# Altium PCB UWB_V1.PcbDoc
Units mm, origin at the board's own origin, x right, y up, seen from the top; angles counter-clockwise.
Board outline 57 x 40.78 mm, 2 copper layers (Top Layer, Bottom Layer); 72 components, 53 nets, 372 pads, 60 vias.
Unrouted connection lines stored in the file: 75.
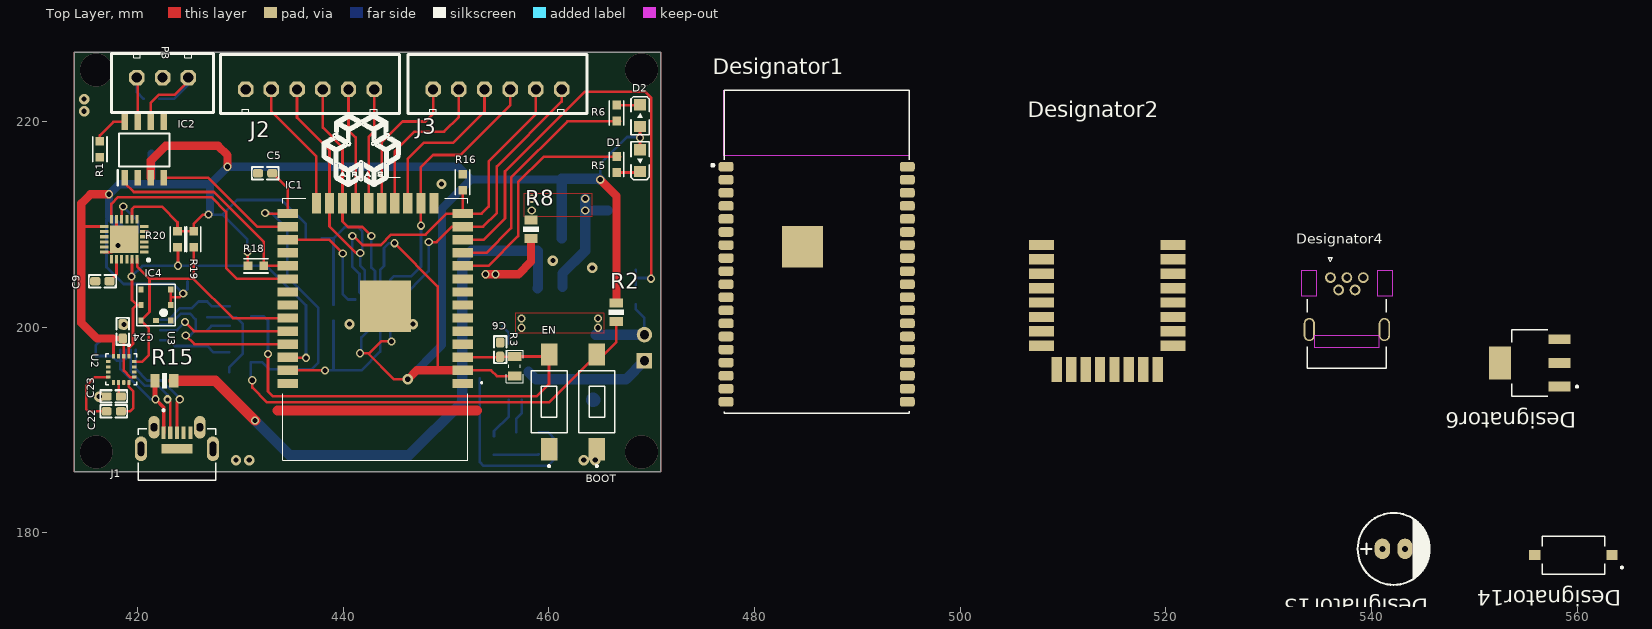
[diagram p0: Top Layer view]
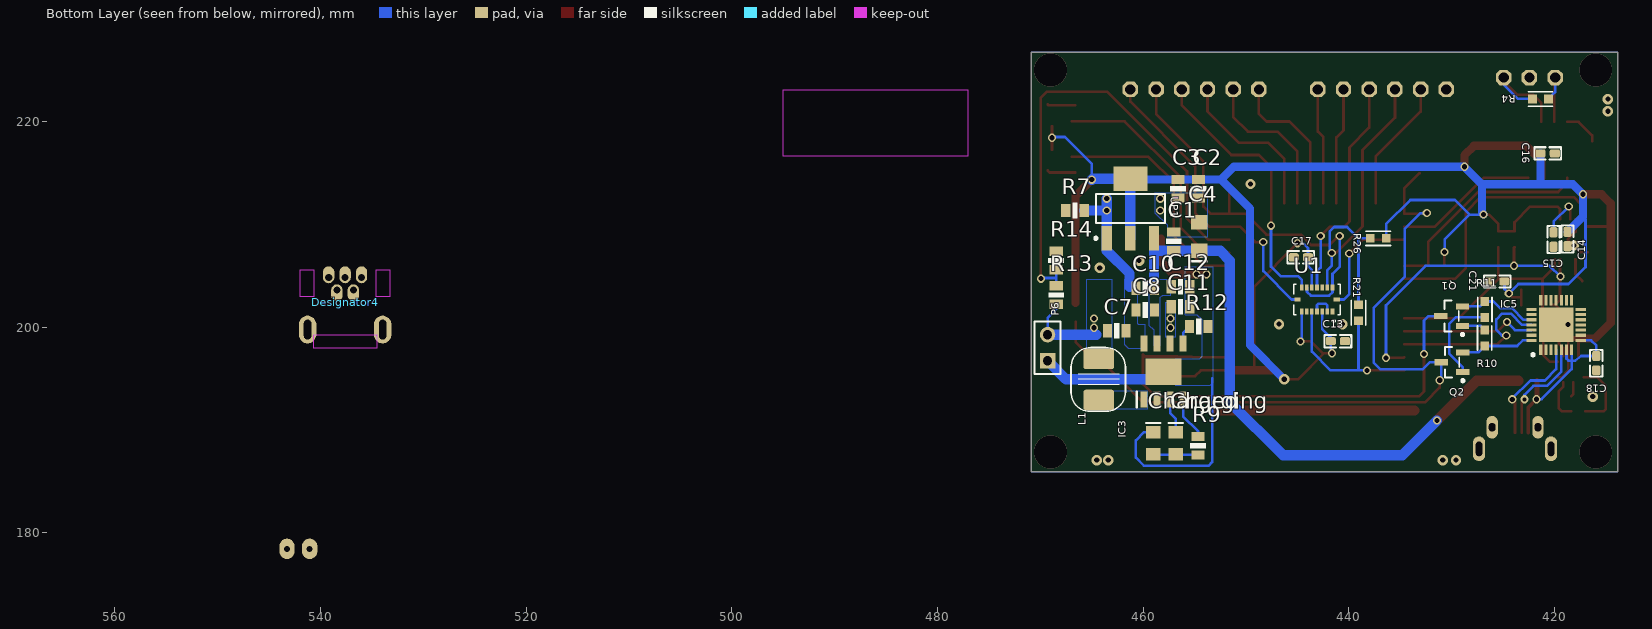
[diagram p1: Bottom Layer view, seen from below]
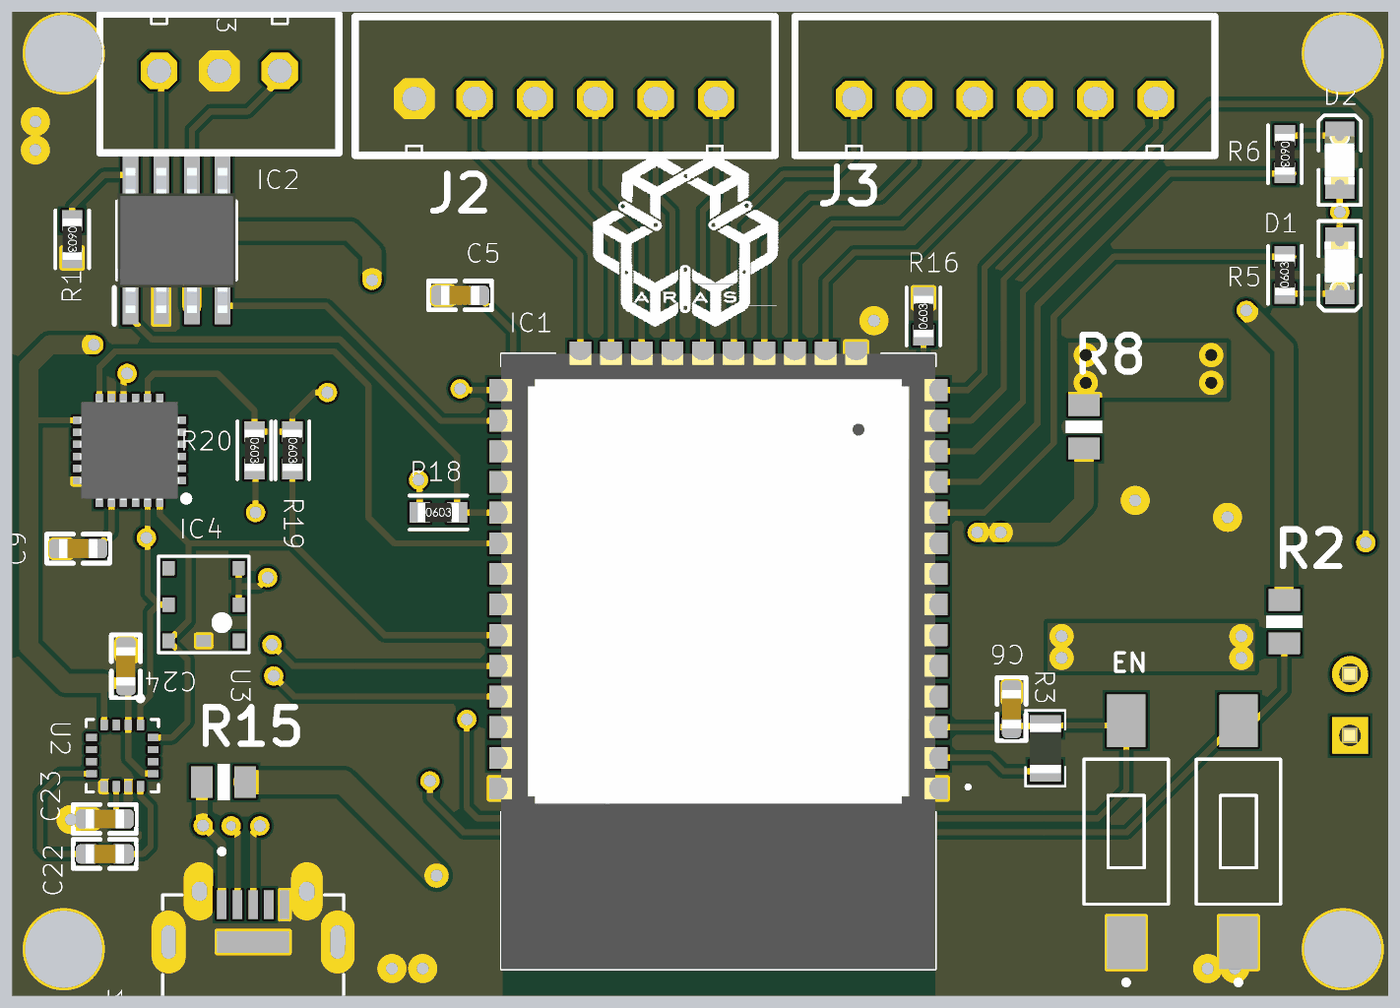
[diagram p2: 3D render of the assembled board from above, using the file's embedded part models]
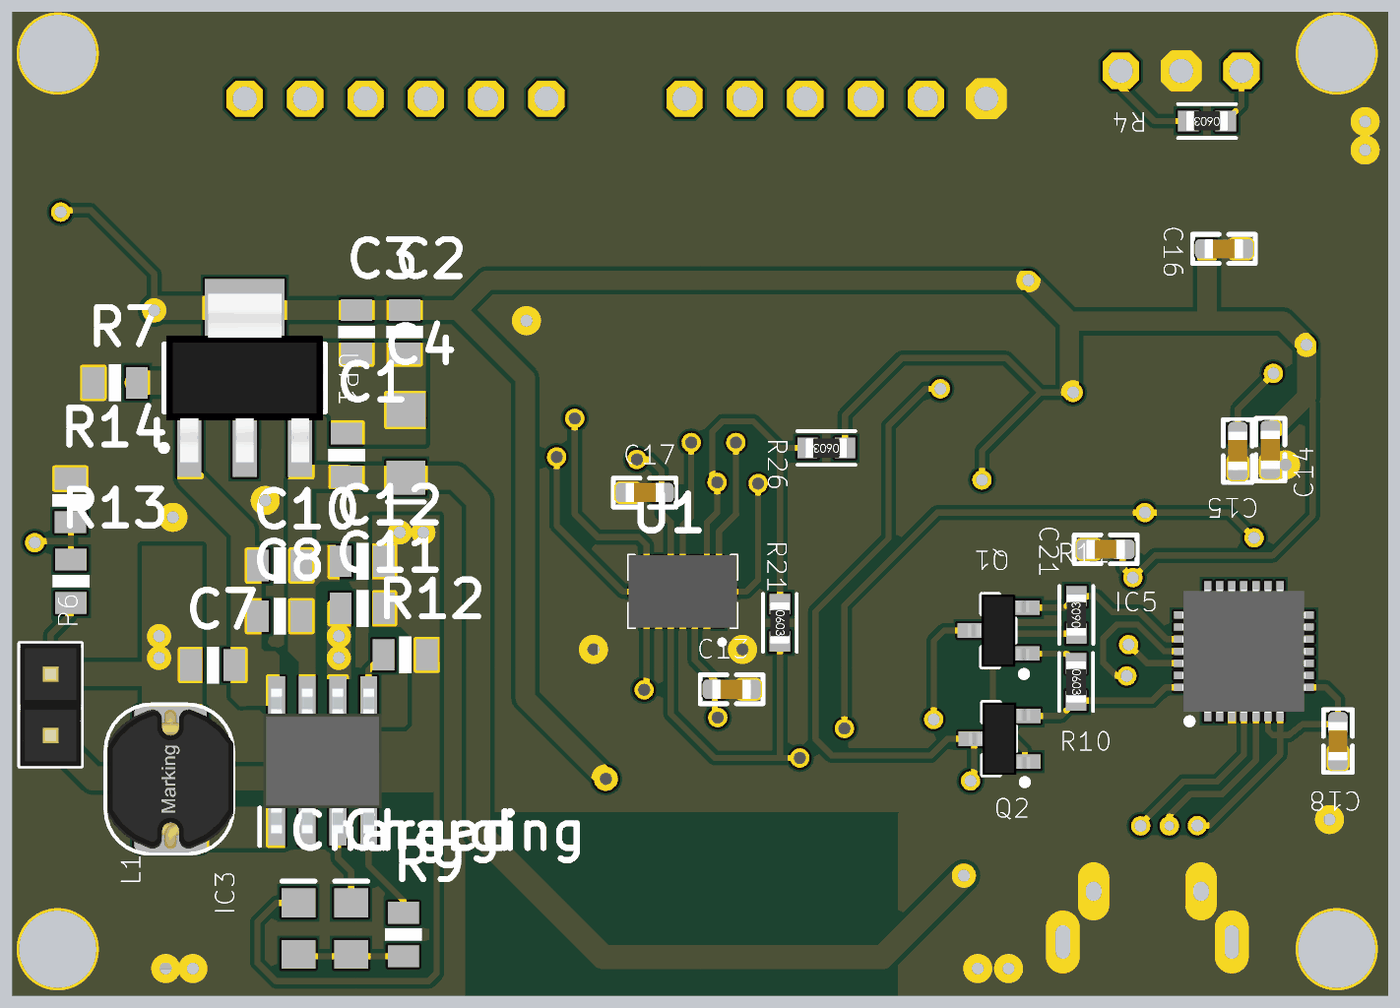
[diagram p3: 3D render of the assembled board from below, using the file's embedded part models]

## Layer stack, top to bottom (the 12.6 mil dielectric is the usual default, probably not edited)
Top Solder: solder mask 0.0102, Solder Resist, Dk 3.5
Top Layer: signal copper 0.0356
Dielectric 1: dielectric 0.32, FR-4, Dk 4.8
Bottom Layer: signal copper 0.0356
Bottom Solder: solder mask 0.0102, Solder Resist, Dk 3.5

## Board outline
413.875,185.95 470.875,185.95 470.875,226.725 413.875,226.725

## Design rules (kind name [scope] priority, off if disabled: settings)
Clearance [All] p1: gap=0.178 ignorepadtopadclearanceinfootprint=TRUE except(0: Arc-Hole Track-Hole SMDPad-Hole THPad-Hole Via-Hole Fill-Hole Poly-Hole Region-Hole Text-Hole)
PolygonConnect [All] p1: connectstyle=Direct reliefconductorwidth=0.254 reliefentries=4 polygonreliefangle="90 Angle" airgapwidth=0.254
RoutingVias [All] p1: holewidth=0.711 width=1.27 viastyle="Through Hole" minholewidth=0.711 minwidth=1.27 maxholewidth=0.711 maxwidth=1.27
SolderMaskExpansion [All] p1: expansion=0.102
Width [All] p1: maxlimit=2 minlimit=0.254 preferedwidth=0.254
30 further rules are at their usual default settings.

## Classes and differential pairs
component class final: BOOT C1 C2 C3 C4 C5 C6 C7 C8 C9 C10 C11 C12 C13 C14 C15 C16 C17 C18 C21 C22 C23 C24 Charged Charging D1 D2 D4 EN IC1 IC2 IC3 IC4 IC5 J1 J2 J3 L1 P3 P6 Q1 Q2 R1 R2 R3 R4 R5 R6 R7 R8 R9 R10 R11 R12 R13 R14 R15 R16 R18 R19 R20 R21 R26 U1 U2 U3 UP1

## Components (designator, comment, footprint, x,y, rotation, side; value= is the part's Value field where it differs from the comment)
BOOT "1437566-4" SW_1437566-4 464.675,192.75 r90 top
C1 "Cap" _0805 457.025,208.35 r90 bottom value=100nf
C2 "Cap" _0805 454.625,213.464 r270 bottom value=22uf
C3 "Cap" _0805 456.616,213.464 r270 bottom value=100NF
C4 "Cap-Pol" _EIA3216 454.575,208.825 r270 bottom value=22uf
C5 "0.1uF" C0603 432.425,214.975 r0 top
C6 "1nf" C0603 455.275,197.825 r270 top
C7 "Cap" _0805 462.575,199.653 r180 bottom value=10uf
C8 "Cap" _0805 459.8,201.678 r0 bottom value=22uf
C9 "220pF" C0603 416.6,204.475 r0 top
C10 "Cap" _0805 459.8,203.778 r0 bottom value=22uf
C11 "Cap" _0805 456.375,202 r180 bottom value=1uf
C12 "Cap" _0805 456.375,203.95 r180 bottom value=1uf
C13 "0.1uF" C0603 441.075,198.65 r0 bottom
C14 "0.1uF" C0603 418.75,208.575 r270 bottom
C15 "0.1uF" C0603 420.1,208.525 r90 bottom
C16 "100nF" C0603 420.675,216.9 r0 bottom
C17 "100nF" C0603 444.675,206.8 r180 bottom
C18 "100nF" C0603 415.95,196.5 r270 bottom
C21 "100nF" C0603 425.575,204.45 r180 bottom
C22 "0.22uF" C0603 417.7,191.825 r180 top
C23 "4.7uF" C0603 417.7,193.275 r0 top
C24 "100nF" C0603 418.575,199.6 r90 top
Charged "LED" _LED-0805 459.025,188.678 r90 bottom
Charging "LED" _LED-0805 456.838,188.678 r90 bottom
D1 "LED SMD PACKAGE" LED_SMD_0805 468.875,216.2 r90 top
D2 "LED SMD PACKAGE" LED_SMD_0805 468.875,220.575 r270 top
Designator1 "Comment" XCVR_ESP32-WROVER-I 486.05,207.35 r0 top
Designator2 "Comment" XCVR_DWM1000 514.3,206.2 r0 top
Designator4 "Comment" MOLEX_54819-0519 536,204.825 r0 top
Designator6 "Comment" SOT230P700X180-4N 555.375,196.525 r180 top
Designator13 "Comment" "cap 02" 542.15,178.45 r180 top
Designator14 "Comment" SW_TS09-63-25-R-160-SMT-TR 559.625,177.85 r180 top
EN "1437566-4" SW_1437566-4 460.025,192.75 r90 top
IC1 "ESP-WROOM-32D" ESPWROOM32D 443.125,199.8 r180 top
IC2 "SN65HVD230D" SOIC127P600X175-8N 420.675,217.25 r90 top
IC3 "ETA9742" SOIC127P600X175-9N 458.025,195.678 r90 bottom
IC4 "MPU-6050" QFN50P400X400X95-25N 418.725,208.55 r180 top
IC5 "CP2102_9" QFN50P500X500X105-29N-D 419.85,200.225 r90 bottom
J1 "UJ2-MIBH2-4-SMT-TR" CUI_UJ2-MIBH2-4-SMT-TR 423.85,187.625 r0 top
J2 "XH_6PIN" XH_6PIN 428.075,220.775 r0 top
J3 "XH_6PIN" XH_6PIN 446.3,220.775 r0 top
L1 "4µ7" "Inductor SMD 3x3.2mm" 464.325,194.928 r90 bottom
P3 "XH_3PIN" XH_3PIN 427.4,226.625 r180 top
P6 "Battery" HDR1X2 469.3,196.735 r90 bottom
Q1 "BC817" SOT23_N 430.011,201.081 r0 bottom
Q2 "BC817" SOT23_N 429.975,196.6 r0 bottom
R1 "Resistor SMD 0603" SMD-0603-RES 416.35,217.3 r180 top value=10K
R2 "Resistor" _0805 466.575,201.45 r270 top value=1K
R3 "10K" RES0805 456.675,196.2 r270 top
R4 "Resistor SMD 0603" SMD-0603-RES 421.375,222.2 r90 bottom value=120
R5 "Resistor SMD 0603" SMD-0603-RES 466.6,215.825 r0 top value=220
R6 "Resistor SMD 0603" SMD-0603-RES 466.6,220.825 r180 top value=220
R7 "Resistor" _0805 466.625,211.35 r0 bottom value=1K
R8 "Resistor" _0805 458.275,209.525 r90 top value=1K
R9 "Resistor" _0805 454.675,188.486 r90 bottom value=1K
R10 "Resistor SMD 0603" SMD-0603-RES 426.8,198.95 r0 bottom value=10K
R11 "Resistor SMD 0603" SMD-0603-RES 426.791,201.728 r180 bottom value=10K
R12 "Resistor" _0805 454.6,200.075 r0 bottom value=1K
R13 "Resistor" _0805 468.45,203.128 r270 bottom value=1K
R14 "Resistor" _0805 468.475,206.478 r270 bottom value=1K
R15 "Resistor" _0805 422.625,194.8 r0 top value=1K
R16 "Resistor SMD 0603" SMD-0603-RES 451.625,214.1 r0 top value=4.7k
R18 "Resistor SMD 0603" SMD-0603-RES 431.525,205.975 r270 top value=4.7k
R19 "Resistor SMD 0603" SMD-0603-RES 425.475,208.55 r180 top value=4.7k
R20 "Resistor SMD 0603" SMD-0603-RES 423.9,208.55 r180 top value=4.7k
R21 "Resistor SMD 0603" SMD-0603-RES 439.075,201.4 r0 bottom value=0
R26 "Resistor SMD 0603" SMD-0603-RES 437.15,208.65 r90 bottom value=4.7k
U1 "BMI088" PQFN50P450X300X100-16N 443.1,202.7 r0 bottom
U2 "HMC5883L-TR" XDCR_HMC5883L-TR 418.427,195.9 r270 top
U3 "BMP180" BMP180 421.8,202.16 r270 top
UP1 "3V3" SOT223_N 461.25,211.55 r90 bottom

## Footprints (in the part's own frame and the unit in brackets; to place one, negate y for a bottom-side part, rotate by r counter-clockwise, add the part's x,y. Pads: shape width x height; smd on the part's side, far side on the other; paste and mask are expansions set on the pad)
_0805 [mm]
  rect 0.9x1.3 smd: 1(-0.9,0) 2(0.9,0)
  silkscreen extent -0.25,-0.76 0.25,0.76
_EIA3216 [mm]
  rect 1.4x1.6 smd: +(1.4,0) -(-1.4,0)
  silkscreen extent 2.41,-0.76 2.41,0.76
_LED-0805 [mil]
  rect 47.24x55.12 smd: A(-40,0) K(44.06,0)
  silkscreen extent 79,-27 79,27
BMP180 [mm]
  rect 0.6x0.5 smd: 1(1.5,1.45) 2(0,1.45) 3(-1.5,1.45) 4(-1.5,-1.45) 5(0,-1.45) 6(1.5,-1.45)
  rect 0.5x0.6 smd: 7(1.5,0)
  silkscreen extent -2,-1.88 2,1.88
C0603 [mm] "CHIP Capacitor, 1.6X0.8mm, 0603 (Make www.tarahiboard.com)"
  rrect50% 1x0.8 smd mask+0.075: 1(-0.7,0) 2(0.7,0)
  silkscreen extent -1.33,-0.6 1.32,0.6, body extent -0.8,-0.4 0.8,0.4, height 0.9
"cap 02" [mm]
  oval 1.5x2 hole 0.6: 1(1.1,0) 2(-1.1,0)
  silkscreen extent -3.5,-3.5 3.5,3.5
CUI_UJ2-MIBH2-4-SMT-TR [mm]
  rect 0.4x1.2 smd: 1(-1.3,2.1) 2(-0.65,2.1) 3(0,2.1) 4(0.65,2.1) 5(1.3,2.1)
  oval 1.2x2.4 hole 0.6 slot 1.4 at 90 deg: SH1(-3.5,0.55) SH4(3.5,0.55)
  oval 1.1x2.2 hole 0.65 slot 0.8 at 90 deg: SH2(-2.225,2.65) SH3(2.225,2.65)
  rect 3x0.9 smd: SH5(0,0.55)
  silkscreen extent -3.75,-2.5 3.75,4.4
ESPWROOM32D [mm]
  rect 2x0.9 smd: 1(-8.5,5.26) 2(-8.5,3.99) 3(-8.5,2.72) 4(-8.5,1.45) 5(-8.5,0.18) 6(-8.5,-1.09) 7(-8.5,-2.36) 8(-8.5,-3.63) 9(-8.5,-4.9) 10(-8.5,-6.17) 11(-8.5,-7.44) 12(-8.5,-8.71) 13(-8.5,-9.98) 14(-8.5,-11.25) 25(8.5,-11.25) 26(8.5,-9.98) 27(8.5,-8.71) 28(8.5,-7.44) 29(8.5,-6.17) 30(8.5,-4.9) 31(8.5,-3.63) 32(8.5,-2.36) 33(8.5,-1.09) 34(8.5,0.18) 35(8.5,1.45) 36(8.5,2.72) 37(8.5,3.99) 38(8.5,5.26)
  rect 0.9x2 smd: 15(-5.715,-12.25) 16(-4.445,-12.25) 17(-3.175,-12.25) 18(-1.905,-12.25) 19(-0.635,-12.25) 20(0.635,-12.25) 21(1.905,-12.25) 22(3.175,-12.25) 23(4.445,-12.25) 24(5.715,-12.25)
  rect 5x5 smd: 39(-1,-2.24)
  silkscreen extent -10.4,-12.75 9,12.75, body extent -9,-12.75 9,12.75, height 3.1
HDR1X2 [mm] "Connector; Header; 2 Position"
  rect 1.5x1.5 hole 0.9: 1(0,0)
  round 1.5 hole 0.9: 2(2.54,0)
  silkscreen extent -1.27,-1.27 3.81,1.27, body extent -1.27,-1.28 3.81,1.26, height 8.79
"Inductor SMD 3x3.2mm" [mm] "Inductor 4.7µH SMD 3x3.2mm"
  round 0.508 on Mech15: 0(0,0)
  rrect25% 2x3 smd: 1(-2,0) 2(2,0)
  silkscreen extent -3.1,-2.6 3.1,2.7, body extent -2.9,-2.6 2.89,2.6, height 4.5
LED_SMD_0805 [mm] "SMD Mono-color Chip LED, body 2.0x1.25mm"
  rect 1.1x1.2 smd: 1(-1.05,0) 2(1.05,0)
  silkscreen extent -1.85,-0.88 1.85,0.88, body extent -1,-0.62 1,0.63, height 0.7
MOLEX_54819-0519 [mm]
  oval 1.1x1.65 smd far side paste-2 mask+0: 1(0,0.275) 2(0.8,-1.475) 3(1.6,0.275) 4(2.4,-1.475) 5(3.2,0.275)
  round 1.05 hole 0.7 mask+0.076: 6(0,0) 7(0.8,-1.2) 8(1.6,0) 9(2.4,-1.2) 10(3.2,0)
  oval 1.122x2.245 hole 0.7 slot 1.9 at 90 deg mask+0: 11(-2.05,-5.05) 12(5.25,-5.05)
  oval 1.7x2.7 smd far side paste-2 mask+0: S1(-2.05,-5.05) S2(5.25,-5.05)
  Keep-Out Layer region: 4.7,-6.8 -1.5,-6.8 -1.5,-5.6 4.7,-5.6
  Keep-Out Layer region: -1.4,-1.8 -2.8,-1.8 -2.8,0.7 -1.4,0.7
  Keep-Out Layer region: 6,-1.8 4.6,-1.8 4.6,0.7 6,0.7
  Keep-Out Layer region: -1.4,-1.8 -2.8,-1.8 -2.8,0.7 -1.4,0.7
  Keep-Out Layer region: 6,-1.8 4.6,-1.8 4.6,0.7 6,0.7
  Keep-Out Layer region: 4.7,-6.8 -1.5,-6.8 -1.5,-5.6 4.7,-5.6
  silkscreen extent -2.25,-8.8 5.45,1.95
PQFN50P450X300X100-16N [mm]
  rect 0.35x0.59 smd: 1(-1.5,1.165) 2(-1,1.165) 3(-0.5,1.165) 4(0,1.165) 5(0.5,1.165) 6(1,1.165) 7(1.5,1.165) 9(1.5,-1.165) 10(1,-1.165) 11(0.5,-1.165) 12(0,-1.165) 13(-0.5,-1.165) 14(-1,-1.165) 15(-1.5,-1.165)
  rect 0.59x0.35 smd: 8(1.915,0) 16(-1.915,0)
  silkscreen extent -2.25,-1.5 2.25,2.2, body extent -2.25,-1.5 2.25,1.5, height 1
QFN50P400X400X95-25N [mm]
  rect 0.8x0.3 smd: 1(-1.95,1.25) 2(-1.95,0.75) 3(-1.95,0.25) 4(-1.95,-0.25) 5(-1.95,-0.75) 6(-1.95,-1.25) 13(1.95,-1.25) 14(1.95,-0.75) 15(1.95,-0.25) 16(1.95,0.25) 17(1.95,0.75) 18(1.95,1.25)
  rect 0.3x0.8 smd: 7(-1.25,-1.95) 8(-0.75,-1.95) 9(-0.25,-1.95) 10(0.25,-1.95) 11(0.75,-1.95) 12(1.25,-1.95) 19(1.25,1.95) 20(0.75,1.95) 21(0.25,1.95) 22(-0.25,1.95) 23(-0.75,1.95) 24(-1.25,1.95)
  rect 2.75x2.65 smd: 25(0,0)
  silkscreen extent -2.48,1.88 -2.23,2.12, body extent -2.05,-2.05 2.05,2.05, height 0.95
QFN50P500X500X105-29N-D [mm]
  rect 1x0.3 smd: 1(-2.4,1.5) 2(-2.4,1) 3(-2.4,0.5) 4(-2.4,0) 5(-2.4,-0.5) 6(-2.4,-1) 7(-2.4,-1.5) 15(2.4,-1.5) 16(2.4,-1) 17(2.4,-0.5) 18(2.4,0) 19(2.4,0.5) 20(2.4,1) 21(2.4,1.5)
  rect 0.3x1 smd: 8(-1.5,-2.4) 9(-1,-2.4) 10(-0.5,-2.4) 11(0,-2.4) 12(0.5,-2.4) 13(1,-2.4) 14(1.5,-2.4) 22(1.5,2.4) 23(1,2.4) 24(0.5,2.4) 25(0,2.4) 26(-0.5,2.4) 27(-1,2.4) 28(-1.5,2.4)
  rect 3.35x3.35 smd: 29(0,0)
  silkscreen extent -3.02,2.13 -2.78,2.38, body extent -2.55,-2.55 2.55,2.55, height 1.05
RES0805 [mm] "Chip Resistor, 2-Leads, Body 2/00x1/25mm, IPC Medium Density DESIGNER:ABBAS BASEREH"
  rect 0.85x1.3 smd: 1(-0.95,0) 2(0.95,0)
  silkscreen extent -1.57,-0.82 1.58,0.83, body extent -1.02,-0.65 1.02,0.65, height 0.5
SMD-0603-RES [mm] "(Make www.tarahiboard.com)"
  rect 0.85x0.85 smd: 1(0,0.775) 2(0,-0.775)
  silkscreen extent -0.7,-1.2 0.7,1.2, body extent -0.4,-0.85 0.4,0.85, height 0.56
SOIC127P600X175-8N [mm]
  rect 1.525x0.65 smd: 1(-2.712,1.905) 2(-2.712,0.635) 3(-2.712,-0.635) 4(-2.712,-1.905) 5(2.712,-1.905) 6(2.712,-0.635) 7(2.712,0.635) 8(2.712,1.905)
  silkscreen extent -3.48,-2.45 1.6,2.58, body extent -3,-2.45 3,2.45, height 1.75
SOIC127P600X175-9N [mm]
  rect 1.55x0.7 smd: 1(-2.725,1.905) 2(-2.725,0.635) 3(-2.725,-0.635) 4(-2.725,-1.905) 5(2.725,-1.905) 6(2.725,-0.635) 7(2.725,0.635) 8(2.725,1.905)
  rect 2.6x3.5 smd: 9(0,0)
  silkscreen extent -3.5,2.61 -1.95,2.61, body extent -3,-2.45 3,2.45, height 1.75
SOT23_N [mm] "SOT23, 3-Leads, Body 2.9x1.3mm, Pitch 0.95mm, Lead Span 2.3mm, IPC Medium Density"
  rect 1.3x0.6 smd: 1(-1.05,0.95) 2(-1.05,-0.95) 3(1.05,0)
  silkscreen extent -1.17,-1.5 0.7,1.92, body extent -1.27,-1.5 1.27,1.5, height 1.1
SOT223_N [mm] "SOT223, 4-Leads, Body 6.5x3.5mm, Pitch 2.3mm, Lead Span 7mm, IPC Medium Density"
  rect 2.4x1 smd: 1(-2.9,2.3) 2(-2.9,0) 3(-2.9,-2.3)
  rect 2.4x3.3 smd: 4(2.9,0)
  silkscreen extent -3.02,-3.35 1.4,3.48, body extent -3.49,-3.24 3.49,3.24, height 1.64
SOT230P700X180-4N [mm]
  rect 2.15x0.95 smd: 1(-2.9,2.3) 2(-2.9,0) 3(-2.9,-2.3)
  rect 2.15x3.25 smd: 4(2.9,0)
  silkscreen extent -4.7,-3.25 1.75,3.25
SW_1437566-4 [mm]
  rect 2.18x1.6 smd: 1(-4.6,0) 2(4.6,0)
  silkscreen extent -6.35,-1.75 3,1.75
SW_TS09-63-25-R-160-SMT-TR [mm]
  rect 1.1x1 smd: 1(-3.75,0) 2(3.75,0)
  silkscreen extent -4.82,-1.85 3.05,1.85
XCVR_DWM1000 [mm]
  rect 2.45x1 smd: 1(-6.4,1.8) 2(-6.4,0.4) 3(-6.4,-1) 4(-6.4,-2.4) 5(-6.4,-3.8) 6(-6.4,-5.2) 7(-6.4,-6.6) 8(-6.4,-8) 17(6.4,-8) 18(6.4,-6.6) 19(6.4,-5.2) 20(6.4,-3.8) 21(6.4,-2.4) 22(6.4,-1) 23(6.4,0.4) 24(6.4,1.8)
  rect 1x2.45 smd: 9(-4.9,-10.295) 10(-3.5,-10.295) 11(-2.1,-10.295) 12(-0.7,-10.295) 13(0.7,-10.295) 14(2.1,-10.295) 15(3.5,-10.295) 16(4.9,-10.295)
XCVR_ESP32-WROVER-I [mm]
  rrect50% 1.45x0.93 smd: 1(-8.81,8.26) 2(-8.81,6.99) 3(-8.81,5.72) 4(-8.81,4.45) 5(-8.81,3.18) 6(-8.81,1.91) 7(-8.81,0.64) 8(-8.81,-0.63) 9(-8.81,-1.9) 10(-8.81,-3.17) 11(-8.81,-4.44) 12(-8.81,-5.71) 13(-8.81,-6.98) 14(-8.81,-8.25) 15(-8.81,-9.52) 16(-8.81,-10.79) 17(-8.81,-12.06) 18(-8.81,-13.33) 19(-8.81,-14.6) 20(8.81,-14.6) 21(8.81,-13.33) 22(8.81,-12.06) 23(8.81,-10.79) 24(8.81,-9.52) 25(8.81,-8.25) 26(8.81,-6.98) 27(8.81,-5.71) 28(8.81,-4.44) 29(8.81,-3.17) 30(8.81,-1.9) 31(8.81,-0.63) 32(8.81,0.64) 33(8.81,1.91) 34(8.81,3.18) 35(8.81,4.45) 36(8.81,5.72) 37(8.81,6.99) 38(8.81,8.26)
  rect 4x4 smd paste-3: 39(-1.38,0.47)
  Keep-Out Layer region: 9,9.33 -9.029,9.33 -9.029,15.7 9,15.7
  Keep-Out Layer region: 9,9.331 -9.03,9.331 -9.03,15.7 9,15.7
  silkscreen extent -10.22,-15.7 9,15.7
XDCR_HMC5883L-TR [mm]
  rrect17% 0.45x0.3 smd: 1(-1.275,0.75) 2(-1.275,0.25) 3(-1.275,-0.25) 4(-1.275,-0.75) 9(1.275,-0.75) 10(1.275,-0.25) 11(1.275,0.25) 12(1.275,0.75)
  rrect17% 0.3x0.45 smd: 5(-0.75,-1.275) 6(-0.25,-1.275) 7(0.25,-1.275) 8(0.75,-1.275) 13(0.75,1.275) 14(0.25,1.275) 15(-0.25,1.275) 16(-0.75,1.275)
  silkscreen extent -2.47,-1.5 1.5,1.5
XH_3PIN [mm]
  oct 1.5x1.5 hole 1: 1(2.45,2.35) 2(4.95,2.35) 3(7.45,2.35)
  silkscreen extent 0,0 9.9,5.75
XH_6PIN [mm]
  oct 1.5x1.5 hole 1: 1(2.45,2.35) 2(4.95,2.35) 3(7.45,2.35) 4(9.95,2.35) 5(12.45,2.35) 6(14.95,2.35)
  silkscreen extent 0,0 17.4,5.75

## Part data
BOOT EN: "Switch Tactile OFF _ON_ SPST Rectangular Button Gull Wing 0.05A 12VDC 1.77N SMD T/R", Contact_Current_Rating="50 mA", Package=None
C1 C2 C3 C7 C8 C10 C11 C12: library part Cap_1
C5 C6 C9 C13 C14 C15 C16 C17 C18 C21 C22 C23 C24: library part "CAP SMD 0805", "CAP 0805"
D1 D2: "SMD Mono-color Chip LED Waterclear", Forward Voltage="3.2 V", Part Number=150080BS75000
IC1: "Integrated Circuit", Manufacturer_Name="Espressif Systems", Mouser Part Number=356-ESP-WROOM-32D
IC2: "Integrated Circuit", Manufacturer_Name="Texas Instruments", Mouser Part Number=595-SN65HVD230D
IC3: "Integrated Circuit", Manufacturer_Name="ETA Solutions"
IC4: "Integrated Circuit", Manufacturer_Name=TDK, Mouser Part Number=410-MPU-6050
IC5: "Integrated Circuit", Manufacturer_Name="Silicon Labs", Manufacturer_Part_Number=CP2102/9
J1: "Micro B, USB 2.0, 1.8 A, Right Angle, Surface Mount _SMT_, USB Receptacle", Package=None
L1: library part "Inductor 4.7µH SMD 3x3.2mm", "Inductor 4.7µH SMD 3x3.2mm", Operating Temperature="-40°C ~ 125°C", Tolerance=±20%
P6: library part "Header 2", "Header, 2-Pin"
Q1 Q2: "45 V, 500 mA NPN general-purpose transistors"
R3: library part "RES SMD PACKAGE", "TOTAL SMD RESISTOR PACK"
U1: "Accelerometer, Gyroscope, 6 Axis Sensor I²C, SPI Output", Package="VFLGA-16 Bosch Sensortec"
U2: "Magnetoresistive Sensor X, Y, Z Axis 16-LCC", Package="LCC-16 Honeywell"
U3: "Pressure Sensor 4.35PSI ~ 15.95PSI _30kPa ~ 110kPa_ Absolute 16 ~ 19 b 7-VLGA", Package="VLGA-7 Bosch Sensortec"
UP1: library part AMS1117-x.x, "x.x Volt, 800mA Low-Dropout Linear Regulator, 4-pin SOT-223"

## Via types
v1: diameter 0.8, hole 0.5, Top Layer to Bottom Layer, 40 vias
v2: diameter 1, hole 0.5, Top Layer to Bottom Layer, 15 vias
v3: diameter 3.2, hole 3.2, Top Layer to Bottom Layer, 4 vias
v4: diameter 0.8, hole 0.4, Top Layer to Bottom Layer, 1 vias

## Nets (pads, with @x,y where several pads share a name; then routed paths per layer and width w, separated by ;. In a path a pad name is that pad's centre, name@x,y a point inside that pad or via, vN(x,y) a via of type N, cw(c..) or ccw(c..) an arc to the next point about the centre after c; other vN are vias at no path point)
3v3: C2.1 C3.1 C13.2 C14.1 C16.2 C17.2 C21.2 C24.1 D1.2 D2.2 IC1.2 IC2.3 IC4.8 IC4.13 R2.1 R3.2 R18.2 R19.2 R20.2 R26.2 U1.3 U1.7 U1.11 U2.2 U2.4 U2.13 U3.2 U3.3 UP1.2 UP1.4 | length 241.6
  Top Layer w0.254: 414.55,209.75 414.6,209.8 IC4.13 ; 417.625,198.9 417.677,198.848 U2.4 ; C24.1 418.677,198.798 U2.2 418.677,195.773 419.295,195.155 419.702,195.155 U2.13 ; IC4.8 419.475,211.475 419.725,211.725 422.375,211.725 423.9,210.2 R20.2 R19.2 425.475,210.05 426.375,210.95 v1(426.925,210.95) ; U3.2 423.25,202.91 ; U3.3 423.25,202.91 ; v1(424.45,203.275) 424.085,202.91 423.25,202.91 ; v1(430.7,207.325) 430.75,207.275 R18.2 ; v1(441.65,197.475) 442.4,197.475 ; v1(444.7,198.625) 443.7,198.625 442.55,197.475 442.4,197.475 ; v1(445,208.175) 449.2,203.975 449.2,195.86 449.25,195.81 ; v2(446.287,194.937) 444.938,194.937 442.4,197.475 ; IC1.2 454.39,195.81 454.95,195.25 R3.2 ; D1.2 v1(468.875,218.425) D2.2
  Top Layer w0.5: 417.625,198.9 C24.1
  Top Layer w0.8: v1(417.25,212.925) 415.425,212.925 414.55,212.05 414.55,209.75 414.55,200.425 416.075,198.9 417.625,198.9 ; IC2.3 421.31,216.21 422.739,217.639 427.861,217.639 428.775,216.725 v1(428.775,215.6) ; v2(446.287,194.937) 447.16,195.81 449.25,195.81 IC1.2 ; v1(465,214.35) 466.575,212.775 R2.1
  Bottom Layer w0.254: 417.25,210.775 417,210.525 417,205.85 418.65,204.2 423.525,204.2 v1(424.45,203.275) 424.875,203.7 C21.2 ; v1(426.925,210.95) 428.275,210.95 ; v1(430.7,207.325) 430.7,208.525 428.275,210.95 ; R26.2 436.375,210.025 434.025,212.375 429.7,212.375 428.275,210.95 ; v1(441.65,197.475) 441.775,197.6 C13.2 441.775,199.025 442.6,199.85 U1.3 ; U1.11 443.6,205.575 443.975,205.95 C17.2 443.975,207.7 444.45,208.175 v1(445,208.175) ; U1.7 444.6,198.725 v1(444.7,198.625) ; v1(465,214.35) 465,215.875 467.625,218.5 v1@469.1,218.5
  Bottom Layer w0.4: C14.1@418.65,209.175 C14.1
  Bottom Layer w0.8: C14.1 417.25,210.775 v1(417.25,212.925) 418.225,213.9 421.325,213.9 ; C16.2 421.375,213.95 421.325,213.9 ; v1(426.925,210.95) 427.075,211.1 427.075,213.9 ; v2(446.287,194.937) 449.625,198.275 449.625,211.55 452.439,214.364 ; UP1.4@461.164,214.364 C3.1 C2.1 452.439,214.364 ; 421.325,213.9 427.075,213.9 ; 427.075,213.9 v1(428.775,215.6) 451.203,215.6 452.439,214.364
  Bottom Layer w1: UP1.4@461.164,214.364 461.25,214.278 UP1.2 ; UP1.4 464.9,214.45 v1(465,214.35)
5V: C1.1 C4.+ C8.1 C10.1 C12.1 IC3.7 R15.2 UP1.3 | length 58.4
  Top Layer w1: R15.2 427.575,194.8 v1(431.45,190.925)
  Bottom Layer w1: v1(431.45,190.925) 434.825,187.55 446.4,187.55 451.575,192.725 451.575,206.475 452.525,207.425 C4.+ 457,207.425 C1.1 458.875,207.45 458.95,207.375 458.95,203.828 C10.1
21: IC1.21 J2.5 | length 11.4
  Top Layer w0.254: J2.5 440.525,219.15 441.22,218.455 IC1.21
AGND: C11.2 C12.2 Charged.K IC3.9 P6.1 R8.1 R12.1 | length 39.3
  Top Layer w0.8: v1(453.85,205.15) v1(454.825,205.15) 457.05,205.15 458.275,206.375 R8.1
  Bottom Layer w0.254: 453.3,195.05 453.3,186.875 453.625,186.55 459.95,186.55 460.725,187.325 460.725,189 459.928,189.797 Charged.K
  Bottom Layer w1: IC3.9 458.753,194.95 467.515,194.95 P6.1
Bat: C7.1 C11.1 IC3.6 L1.2 P6.2 R13.2 | length 8
  Bottom Layer w0.254: R13.2 468.45,201.75 469.3,200.9 P6.2
  Bottom Layer w1: 464.575,199.275 P6.2
  other v1: 457.35,199.95 464.8,199.95 457.35,200.85 464.8,200.85
Bat_Sense: IC1.12 R13.1 R14.2 | length 47.9
  Top Layer w0.254: IC1.12 453.685,208.51 455.75,210.575 455.75,215.15 463.5,222.9 469.375,222.9 469.95,222.325 v1(469.95,204.725)
  Bottom Layer w0.254: R13.1 468.45,204.791 ; R14.2 468.45,205.553 468.45,204.791 ; v1(469.95,204.725) 469.884,204.791 468.45,204.791
"CAN RX": IC1.26 IC2.4 | length 14
  Top Layer w0.254: IC2.4 426.887,214.538 431.645,209.78 IC1.26
"CAN TX": IC1.29 IC2.1 R18.1 | length 21.1
  Top Layer w0.254: IC2.1 418.77,214.03 419.65,213.15 427.45,213.15 432.3,208.3 R18.1 432.305,205.97 IC1.29
CS_ACC: IC1.23 J2.3 R21.2 R26.1 U1.14 | length 35.5
  Top Layer w0.254: J2.3 435.525,220.375 438.68,217.22 IC1.23 438.68,209.795 441.25,207.225 v1(441.675,207.225)
  Bottom Layer w0.254: R26.1 439.075,208.65 ; R21.2 439.075,208.65 ; U1.14 442.1,205.55 441.675,205.975 v1(441.675,207.225) 441.875,207.425 441.875,209.325 441.45,209.75 440.175,209.75 439.075,208.65
CS_GYR: IC1.37 R21.1 U1.5 | length 18.5
  Top Layer w0.254: IC1.37 438.24,195.81 v1(438.25,195.8)
  Bottom Layer w0.254: v1(438.25,195.8) 439.075,195.8 ; R21.1 439.075,195.8 ; U1.5 443.6,197.625 441.775,195.8 439.075,195.8
EN: C6.2 EN.2 IC1.3 Q1.3 R3.1 | length 48.1
  Top Layer w0.254: v1(432.7,197.4) 432.7,193.75 433.15,193.3 458.85,193.3 460.025,194.475 EN.2 459.825,197.15 R3.1 456.65,197.125 C6.2 455.23,197.08 IC1.3
  Bottom Layer w0.254: Q1.3 432.269,201.081 432.7,200.65 v1(432.7,197.4)
GND: BOOT.1 C5.1 C6.1 C9.1 C13.1 C14.2 C15.1 C16.1 C17.1 C18.2 C21.1 C23.1 C24.2 EN.1 IC1.1 IC1.15 IC1.38 IC1.39 IC2.2 IC4.11 IC4.18 IC4.25 IC5.3 IC5.29 J1.5 J1.SH1 J1.SH2 J1.SH3 J1.SH4 J1.SH5 J2.1 P3.2 R1.1 R7.2 R14.1 R16.1 U1.2 U1.4 U1.6 U2.9 U2.11 U3.7 | length 26.4
  Top Layer w0.254: IC4.18 416.775,207.305 417.48,207.305 IC4.25 417.975,209.3 IC4.11
  Top Layer w1: 433.625,191.9 453,191.9
  Bottom Layer w0.254: U1.2 442.1,202.125 442.275,202.3 442.95,202.3 443.1,202.15 U1.4
  other v2: 429.6,187.075 430.875,187.075 463.4,187.075 464.525,187.075 416.3,193.25 418.7,200.25 440.625,200.3 446.8,200.3 464.225,205.775 460.4,206.475 418.125,207.95 449.575,213.925 414.825,221 414.825,222.175
  other v3: 416,187.875 469,187.875 416,225 469,225
INT1: IC1.27 U1.16 | length 11.3
  Top Layer w0.254: IC1.27 438.64,208.51 v1(439.975,207.175)
  Bottom Layer w0.254: v1(439.975,207.175) 439.975,203.2 440.475,202.7 U1.16
INT2: IC1.22 J2.4 U1.12 | length 22.2
  Top Layer w0.254: J2.4 438.025,219.4 439.95,217.475 IC1.22 439.95,210.3 440.5,209.75 441.875,209.75 v1(442.75,208.875)
  Bottom Layer w0.254: v1(442.75,208.875) 442.75,205.8 443.1,205.45 U1.12
INT_MPU: IC1.30 IC4.12 | length 25.4
  Top Layer w0.254: IC4.12 417.475,212 418.125,212.65 427.2,212.65 428.625,211.225 428.625,205.775 429.7,204.7 IC1.30
IO0: BOOT.2 C5.2 IC1.25 Q2.3 R2.2 | length 73.9
  Top Layer w0.254: v1(431.175,194.85) 431.175,194.125 432.575,192.725 460.05,192.725 BOOT.2 465.35,197.35 466.575,198.575 R2.2 ; v1(432.425,211.1) 432.475,211.05 IC1.25 434.625,213.475 C5.2
  Bottom Layer w0.254: v1(431.175,194.85) 431.025,195 Q2.3 432.125,196.6 432.825,195.9 436.925,195.9 437.6,196.575 437.6,201.875 434.575,204.9 434.575,209.575 433.05,211.1 v1(432.425,211.1)
IO1: IC1.24 J2.2 | length 12.9
  Top Layer w0.254: J2.2 433.025,220.975 437.41,216.59 IC1.24
IO5: IC1.20 J2.6 | length 11.3
  Top Layer w0.254: IC1.20 442.49,218.49 443.025,219.025 J2.6
IO6: IC1.19 J3.1 | length 14.4
  Top Layer w0.254: IC1.19 443.76,217.96 445.8,220 448,220 448.75,220.75 J3.1
IO7: IC1.18 J3.2 | length 15.4
  Top Layer w0.254: IC1.18 445.03,217.13 446.925,219.025 449.825,219.025 451.25,220.45 J3.2
IO8: IC1.17 J3.3 | length 15.8
  Top Layer w0.254: IC1.17 446.3,216.4 447.85,217.95 450.725,217.95 453.75,220.975 J3.3
IO9: IC1.16 J3.4 U1.9 | length 26.7
  Top Layer w0.254: v1(447.575,209.875) 447.57,209.88 IC1.16 447.57,215.57 448.75,216.75 451.425,216.75 456.25,221.575 J3.4
  Bottom Layer w0.254: U1.9 444.6,204.625 444.925,204.95 446.625,204.95 447.575,205.9 v1(447.575,209.875)
IO10: IC1.14 J3.5 R16.2 U1.10 U1.15 | length 39.7
  Top Layer w0.254: v1(440.9,208.875) 441.022,208.875 441.897,208 443.675,208 444.675,209 448.025,209 450.075,211.05 IC1.14 ; R16.2 IC1.14 ; J3.5 458.75,220.725 454.15,216.125 454.15,211.725 453.475,211.05 IC1.14
  Bottom Layer w0.254: v1(440.9,208.875) 440.9,205.95 440.875,205.925 441.6,205.2 U1.15 441.6,203.4 441.925,203.075 443.711,203.075 444.08,203.444 444.08,203.845 U1.10
IO11: IC1.13 J3.6 U1.8 | length 29.7
  Top Layer w0.254: v1(448.325,208.275) 449.1,208.275 450.605,209.78 IC1.13 453.605,209.78 454.95,211.125 454.95,215.625 461.25,221.925 J3.6
  Bottom Layer w0.254: U1.8 445.575,202.7 448.325,205.45 v1(448.325,208.275)
NetC9_2: C9.2 IC4.20 | length 2.4
  Top Layer w0.254: C9.2 417.975,205.15 IC4.20
NetC15_2: C15.2 IC4.10 | length 4.4
  Top Layer w0.254: IC4.10 418.475,211.59 v1(418.625,211.74)
  Bottom Layer w0.254: v1(418.625,211.74) 420.1,210.265 C15.2
NetC18_1: C18.1 IC5.6 IC5.7 IC5.8 J1.1 R15.1 | length 18.7
  Top Layer w0.35: v1@421.725,193.05 v1(421.775,193) 422.55,192.225 J1.1
  Top Layer w0.5: v1@421.725,193.05 R15.1
  Bottom Layer w0.254: IC5.8 416.45,198.725 415.95,198.225 C18.1 417.417,197.2 417.992,196.75 418.35,196.75 ; IC5.7 418.35,196.75 ; IC5.6 418.85,196.95 418.65,196.75 418.35,196.75 ; v1(421.775,193) 421.275,193 418.35,195.925 418.35,196.75
NetC22_1: C22.1 U2.12 | length 4
  Top Layer w0.254: C22.1 419.285,191.825 419.6,192.14 419.6,193.775 419.177,194.198 U2.12
NetC22_2: C22.2 U2.8 | length 6.8
  Top Layer w0.254: C22.2 415.25,191.825 415.025,192.05 415.025,194.3 415.875,195.15 U2.8
NetC23_2: C23.2 U2.10 | length 1.4
  Top Layer w0.254: U2.10 418.177,193.498 C23.2
NetCharged_A: Charged.A Charging.A R9.1 | length 4.4
  Bottom Layer w0.254: R9.1 458.949,187.586 Charged.A
NetCharging_K: Charging.K IC3.3 | length 3.4
  Bottom Layer w0.254: Charging.K 456.838,191.088 457.39,191.64 IC3.3
NetD1_1: D1.1 R5.2 | length 2.8
  Top Layer w0.254: R5.2 469.1,215.05 D1.1@469.3,215.25
NetD2_1: D2.1 R6.2 | length 2.7
  Top Layer w0.254: R6.2 469.225,221.6 D2.1@469.3,221.675
NetIC1_10: IC1.10 R5.1 | length 22.8
  Top Layer w0.254: IC1.10 454.145,205.97 457.025,208.85 457.025,214.1 459.5,216.575 R5.1@466.95,216.575
NetIC1_11: IC1.11 R6.1 | length 23.5
  Top Layer w0.254: IC1.11 453.94,207.24 456.35,209.65 456.35,214.55 461.825,220.025 R6.1@466.95,220.025
NetIC2_6: IC2.6 P3.1 R4.1 | length 10.8
  Top Layer w0.254: IC2.6 421.31,221.835 422.074,222.599 423.624,222.599 424.95,223.925 P3.1
  Bottom Layer w0.254: R4.1 423.55,222.2 424.95,223.6 P3.1
NetIC2_7: IC2.7 P3.3 R4.2 | length 6.7
  Top Layer w0.254: P3.3 420.04,224.185 IC2.7
  Bottom Layer w0.254: P3.3 419.95,222.85 R4.2
NetIC2_8: IC2.8 R1.2 | length 3.5
  Top Layer w0.254: R1.2 416.35,218.65 417.662,219.962 IC2.8
NetIC3_1: IC3.1 L1.1 | length 0
  Bottom Layer w1.4: L1.1@464.3,192.953 L1.1
NetIC3_4: IC3.4 R9.2 | length 4.2
  Bottom Layer w0.254: R9.2 454.675,189.9 456.12,191.345 IC3.4
NetIC3_5: IC3.5 R12.2 | length 1.9
  Bottom Layer w0.254: R12.2 456.12,199.455 IC3.5
NetIC5_4: IC5.4 J1.3 | length 10.7
  Top Layer w0.254: J1.3 423.85,192.713 v1(424.125,192.988)
  Bottom Layer w0.254: IC5.4 419.85,195.925 420.95,194.825 422.35,194.825 v1@424.125,193.05
NetIC5_5: IC5.5 J1.2 | length 10.5
  Top Layer w0.254: v4(422.938,192.988) 423.2,192.725 J1.2
  Bottom Layer w0.254: IC5.5 419.35,195.7 420.75,194.3 422.05,194.3 422.938,193.412 v4(422.938,192.988)
NetIC5_24: IC5.24 Q1.2 R11.1 | length 7.6
  Bottom Layer w0.254: IC5.24 423.039,200.725 424.164,201.85 425.3,201.85 425.953,202.503 R11.1 427.262,202.031 Q1.2
NetIC5_28: IC5.28 Q2.2 R10.1 | length 7.2
  Bottom Layer w0.254: IC5.28 423.1,198.725 423.65,198.175 R10.1 427.425,197.55 Q2.2
NetQ1_1: Q1.1 R10.2 | length 2.3
  Bottom Layer w0.254: R10.2 427.206,200.131 Q1.1
NetQ2_1: Q2.1 R11.2 | length 8.9
  Bottom Layer w0.254: R11.2 429.622,200.953 430.25,200.325 430.25,197.425 428.925,196.1 Q2.1
PGND: C1.2 C2.2 C3.2 C4.- C7.2 C8.2 C10.2 IC3.8 R7.1 R8.2 UP1.1 | length 11.7
  Bottom Layer w1: 461.325,203.925 461.325,205.225 463.55,207.45 UP1.1 v1(463.55,211.35) ; v1(463.55,212.5) v1(463.55,211.35) ; R7.1 v1(463.55,211.35)
  other v1: 458.35,211.35 458.35,212.5
RXD0: IC1.35 IC5.25 | length 16.6
  Top Layer w0.254: v1(424.7,199.2) 425.55,198.35 IC1.35
  Bottom Layer w0.254: IC5.25 423.15,200.225 424.25,201.325 425.125,201.325 425.675,200.775 425.675,199.75 425.125,199.2 v1(424.7,199.2)
SCL: IC1.36 IC4.23 R20.1 U2.1 U3.5 | length 38.1
  Top Layer w0.254: U2.1 419.177,197.977 419.575,198.375 419.575,201.825 419.91,202.16 419.94,202.16 ; IC4.23 419.475,202.625 419.94,202.16 ; U3.5 419.94,202.16 ; R20.1 423.95,207.725 v1(423.95,205.975) ; IC1.36 434.68,197.025 v1(436.4,197.025)
  Bottom Layer w0.254: v1(419.425,204.925) 420.475,205.975 v1(423.95,205.975) 432.55,205.975 436.4,202.125 v1(436.4,197.025)
SDA: IC1.33 IC4.24 R19.1 U2.16 U3.6 | length 30.3
  Top Layer w0.254: U2.16 420.475,196.65 421.125,197.3 421.125,199.885 U3.6 421.175,201.485 421.175,204.7 ; IC4.24 419.975,205.9 421.175,204.7 ; R19.1 425.475,204.7 ; IC1.33 429.285,200.89 425.475,204.7 ; 421.175,204.7 425.475,204.7
TXD0: IC1.34 IC5.26 | length 13.1
  Top Layer w0.254: v1(424.625,200.5) 425.505,199.62 IC1.34
  Bottom Layer w0.254: IC5.26 423.85,199.725 v1(424.625,200.5)
pads on no net: Designator1.1 Designator1.2 Designator1.3 Designator1.4 Designator1.5 Designator1.6 Designator1.7 Designator1.8 Designator1.9 Designator1.10 Designator1.11 Designator1.12 Designator1.13 Designator1.14 Designator1.15 Designator1.16 Designator1.17 Designator1.18 Designator1.19 Designator1.20 Designator1.21 Designator1.22 Designator1.23 Designator1.24 Designator1.25 Designator1.26 Designator1.27 Designator1.28 Designator1.29 Designator1.30 Designator1.31 Designator1.32 Designator1.33 Designator1.34 Designator1.35 Designator1.36 Designator1.37 Designator1.38 Designator1.39 Designator2.1 Designator2.2 Designator2.3 Designator2.4 Designator2.5 Designator2.6 Designator2.7 Designator2.8 Designator2.9 Designator2.10 Designator2.11 Designator2.12 Designator2.13 Designator2.14 Designator2.15 Designator2.16 Designator2.17 Designator2.18 Designator2.19 Designator2.20 Designator2.21 Designator2.22 Designator2.23 Designator2.24 Designator4.1 Designator4.2 Designator4.3 Designator4.4 Designator4.5 Designator4.6 Designator4.7 Designator4.8 Designator4.9 Designator4.10 Designator4.11 Designator4.12 Designator4.S1 Designator4.S2 Designator6.1 Designator6.2 Designator6.3 Designator6.4 Designator13.1 Designator13.2 Designator14.1 Designator14.2 IC1.4 IC1.5 IC1.6 IC1.7 IC1.8 IC1.9 IC1.28 IC1.31 IC1.32 IC2.5 IC3.2 IC4.1 IC4.2 IC4.3 IC4.4 IC4.5 IC4.6 IC4.7 IC4.9 IC4.14 IC4.15 IC4.16 IC4.17 IC4.19 IC4.21 IC4.22 IC5.1 IC5.2 IC5.9 IC5.10 IC5.11 IC5.12 IC5.13 IC5.14 IC5.15 IC5.16 IC5.17 IC5.18 IC5.19 IC5.20 IC5.21 IC5.22 IC5.23 IC5.27 J1.4 L1.0 U1.1 U1.13 U2.3 U2.5 U2.6 U2.7 U2.14 U2.15 U3.1 U3.4

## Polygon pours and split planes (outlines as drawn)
Bat on Top Layer "Bottom Layer-No Net" (solid, remove dead copper, shelved, pour order 12): 456.775,201.4 465.35,201.4 465.35,199.4 456.775,199.4
PGND on Top Layer "Bottom Layer-No Net" (solid, remove dead copper, shelved, pour order 18): 457.625,213.025 464.2,213.025 464.2,210.725 457.625,210.725
GND on Top Layer "Bottom Layer-No Net" (solid, remove dead copper, shelved, pour order 22): 413.875,185.95 413.875,226.725 470.875,226.725 470.875,185.95
NetIC3_1 on Bottom Layer "Bottom Layer-No Net" (solid, remove dead copper, shelved, pour order 0): 459.575,193.775 463.5,193.775 463.5,191.85 463.475,191.825 463.225,192.075 459.575,192.075
Bat on Bottom Layer "Bottom Layer-No Net" (solid, remove dead copper, shelved, pour order 2): 465.525,196.25 463.05,196.25 463,196.3 463,204.6 465.525,204.6
PGND on Bottom Layer "Bottom Layer-No Net" (solid, remove dead copper, shelved, pour order 6): 459.8,197.975 459.8,200.225 460.45,200.225 460.55,200.325 460.55,204.6 461.825,204.6 461.825,198.325 461.45,197.95
5V on Bottom Layer "Bottom Layer-No Net" (solid, remove dead copper, shelved, pour order 8): 458.325,198.25 458.325,202.9 458.1,203.125 457.325,203.125 457.325,204.475 457.475,204.625 459.45,204.625 459.45,200.2 459,199.75 459,198.25
Bat on Bottom Layer "Bottom Layer-No Net" (solid, remove dead copper, shelved, pour order 10): 456.85,199.075 456.85,202.4 457.85,202.4 457.85,199.075
PGND on Bottom Layer "Bottom Layer-No Net" (solid, remove dead copper, shelved, pour order 16): 457.675,208.8 453.75,208.8 453.75,213 453.725,213.025 458.875,213.025 458.875,211.15 457.675,209.95
AGND on Bottom Layer "Bottom Layer-No Net" (solid, remove dead copper, shelved, pour order 14): 456.9,194.375 453.475,194.375 453.175,194.675 453.175,205.85 455.975,205.85 455.975,201.275 455.925,201.225 454.775,201.225 454.325,200.775 454.325,197.15 454.575,196.9 456.9,196.9
GND on Bottom Layer "Bottom Layer-No Net" (solid, remove dead copper, shelved, pour order 20): 413.875,226.725 470.875,226.725 470.875,185.95 413.875,185.95

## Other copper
Top Layer:
  pour cut-out: 434.125,193.55 434.175,193.5 434.175,185.9 434.225,185.95 452.15,185.95 452.125,185.975 452.125,193.55
Bottom Layer:
  pour cut-out: 443.95,193.175 444,193.125 444,185.525 444.05,185.575 461.975,185.575 461.95,185.6 461.95,193.175
  pour cut-out: 448.4,226.725 470.875,226.725

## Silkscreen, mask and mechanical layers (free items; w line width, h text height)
Top Overlay:
  drawing of 1429 lines, arcs and shapes, not listed
Mechanical 15:
  lines w0.05: 442.499,188.55 442.499,193.75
